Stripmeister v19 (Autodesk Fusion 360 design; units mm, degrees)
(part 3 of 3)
base_feature "Base Feature1"
base_feature "Base Feature2"
base_feature "Base Feature2"
base_feature "Base Feature3"
base_feature "Base Feature4"
base_feature "Base Feature2"
base_feature "Base Feature3"
base_feature "Base Feature4"
fillet "Fillet1" radius 0.0254
create_component "CreateComponent1"
create_component "CreateComponent2"
create_component "CreateComponent3"
create_component "CreateComponent4"
remove_body "RemoveBody1"
create_component "CreateComponent5"
remove_body "RemoveBody1"
create_component "CreateComponent1"
create_component "CreateComponent1"
create_component "CreateComponent6"
create_component "CreateComponent1"
create_component "CreateComponent7"
create_component "CreateComponent8"
create_component "CreateComponent9"
create_component "CreateComponent1"
create_component "CreateComponent2"
create_component "CreateComponent1"
create_component "CreateComponent10"
remove_instance "RemoveInstance1"
remove_instance "RemoveInstance2"
remove_instance "RemoveInstance3"
remove_instance "RemoveInstance4"
remove_instance "RemoveInstance5"
named bodies: "Wheel Block", "Wheel Pin", "Locking Pin", "Wheel Screw", "Cutter Wheel", "Knob", "Knob (1)"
